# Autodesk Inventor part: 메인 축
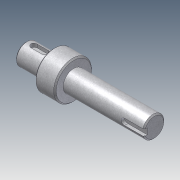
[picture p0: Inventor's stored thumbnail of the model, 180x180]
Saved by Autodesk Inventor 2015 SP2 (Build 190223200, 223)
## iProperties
Company: 한국ATC센터
Created: 2014-10
Part Number: 메인 축
Document SubType Name: Modeling
Designer: KYOUNG IL JANG
Density: 7.85 g/cm^3
Mass: 229.947 g
Surface Area: 74.3518 cm^2
Volume: 29.2926 cm^3
Material: 강철
Appearance: 금속-강(스테인리스, 브러시됨)
Author: KYOUNG IL JANG
Revision Number: 1
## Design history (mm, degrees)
sketch "스케치1"
  geometry: L1 (10.497, -57.5)-(112.497, -57.5); L2 (10.497, -66)-(32.497, -66); L3 (32.497, -72.5)-(46.5, -72.5); L4 (46.5, -66)-(112.497, -66); L5 (112.497, -66)-(112.497, -57.5); L6 (10.497, -66)-(10.497, -57.5); L7 (46.5, -69.749)-(46.5, -45.251) reference; L8 (46.5, -72.5)-(46.5, -66); L9 (32.497, -72.5)-(32.497, -66); L10 (32.497, -35)-(32.497, -80) reference; 3 further points
  constraints: 16 end point, 3 point on line, 2 parallel, 2 perpendicular, 1 collinear, 1 horizontal, 1 midpoint
  dimensions: "d0" = 17 diameter of L4 L1; "d1" = 30 diameter of L3 L1; "d2" = 22 distance of L2.start L2.end; "d3" = 65.99692 distance of L4.start L4.end (derived); "d5" = 17 diameter of L2 L1; "d19" = 80 distance between parallel lines of L5 L9
revolve "회전1" sketch "스케치1" stored, may be unused: angle "d4" = 90 deg
chamfer "모따기1" distance "d6" = 1; stored, may be unused: second distance "d7" = 2, angle "d8" = 45 deg
node "작업 평면1"
sketch "스케치2"
  geometry: L1 (-11, -7.5)-(-11, 7.5) reference; L2 (-4.5, 2.5)-(4.5, 2.5); L3 (4.5, -2.5)-(-4.5, -2.5); A1 r 2.5 centre (4.5, 0) between (4.5, -2.5) and (4.5, 2.5); A2 r 2.5 centre (-4.5, 0) between (-4.5, 2.5) and (-4.5, -2.5); 2 further points
  constraints: 4 end point, 4 point on circle, 4 tangent, 2 centre point, 1 horizontal alignment, 1 midpoint, 1 parallel, 1 perpendicular
  dimensions: "d9" = 5 distance between parallel lines of L3 L2; "d10" = 14 dimension on A1 A2; "d11" = 4 distance edge to line of A2 L1
extrude "돌출1" cut sketch "스케치2" distance "d12" = 3; taper "d13" = 0 deg
node "작업 평면2"
sketch "스케치3"
  geometry: L1 (32.998, 7.5)-(32.998, -7.5) reference; L2 (32.998, 2.5)-(17.498, 2.5); L3 (17.498, -2.5)-(32.998, -2.5); A1 r 2.5 centre (17.498, 0) between (17.498, 2.5) and (17.498, -2.5); 2 further points
  constraints: 4 end point, 2 perpendicular, 2 point on circle, 2 point on line, 2 tangent, 1 centre point, 1 horizontal alignment, 1 midpoint
  dimensions: "d14" = 5 distance between parallel lines of L3 L2; "d15" = 18 dimension on A1 L1
extrude "돌출2" cut sketch "스케치3" distance "d16" = 3; taper "d17" = 0 deg
node "솔리드1"
node "참조4"
node "참조5"
